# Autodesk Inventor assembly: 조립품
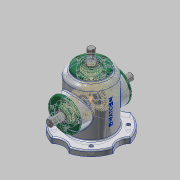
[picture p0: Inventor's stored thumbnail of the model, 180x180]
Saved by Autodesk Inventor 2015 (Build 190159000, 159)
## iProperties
Created: 2022-04
Part Number: 조립품
Document SubType Name: Assembly
Designer: User
Author: User
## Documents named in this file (16)
- C:\Users\User\Desktop\720406V1003\조립품.iam
- C:\Users\User\Desktop\720406V1003\본체.ipt
- C:\Users\User\Desktop\720406V1003\메인 베벨기어.ipt
- C:\Users\User\Desktop\720406V1003\메인 축.ipt
- 메인 축.ipt
- C:\Users\User\Desktop\720406V1003\베어링 6203.ipt
- C:\Users\User\Desktop\720406V1003\볼트 M4.ipt
- 볼트 M4.ipt
- C:\Users\User\Desktop\720406V1003\서브 베벨기어.ipt
- C:\Users\User\Desktop\720406V1003\서브 축.ipt
- 서브 축.ipt
- C:\Users\User\Desktop\720406V1003\오일 실.ipt
- 오일 실.ipt
- C:\Users\User\Desktop\720406V1003\커버.ipt
- C:\Users\User\Desktop\720406V1003\키 4x4.ipt
- C:\Users\User\Desktop\720406V1003\키 5x5.ipt
